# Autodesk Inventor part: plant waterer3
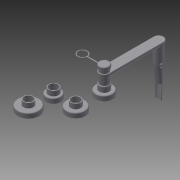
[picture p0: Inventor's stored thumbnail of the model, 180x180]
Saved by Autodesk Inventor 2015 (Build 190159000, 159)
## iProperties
Created: 2014-06
Part Number: plant waterer3
Material: Generic
Document SubType Name: Modeling
Designer: Kay
Density: 1 g/cm^3
Appearance: Default
Author: Kay
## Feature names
1. Loft2
2. Extrusion18
3. Sweep2
4. Extrusion19
5. Extrusion20
6. Extrusion21
7. Extrusion22
8. Extrusion23
9. Extrusion25
10. Extrusion26
11. Extrusion27
12. Extrusion28
13. Fillet1
14. Split1
15. Extrusion30
16. Extrusion31
17. Extrusion32
18. Revolution2
19. Fillet2
20. Extrusion33
21. Extrusion34
22. Revolution3
23. Extrusion35
24. Extrusion36
25. Fillet3
26. Extrusion37
27. Extrusion38
28. Extrusion39
29. Extrusion40
30. Extrusion41
31. Fillet4
32. Extrusion42
33. Extrusion43
34. Extrusion44
35. Revolution4
36. Coil2
37. Fillet5
38. Extrusion45
39. Extrusion46
40. Extrusion47
41. Fillet6
42. Fillet7
43. Fillet8
44. Fillet9
45. Fillet10
46. Fillet11
47. Fillet12
48. Fillet13
49. Extrusion48
50. Extrusion49
51. Extrusion50
52. Revolution5
53. Coil3
54. Fillet14
55. Revolution6
56. Coil4
## Parameters: d45 = 23 mm, d166 = 65 mm, d167 = 7.5 mm, d168 = 15 mm, d169 = 7.5 mm, d170 = -65 mm, d171 = 15 mm, d172 = 18 mm, d173 = 1.5 mm, d174 = 0.5 mm, d175 = 1.5 mm, d176 = -35 mm, d177 = 7.5 mm, d178 = 1.5 mm, d179 = 0, d180 = 90 deg, d181 = 0, d182 = 90 deg, d183 = 0, d184 = 90 deg, d185 = 0, d186 = 90 deg, d187 = 0, d188 = 90 deg, d189 = 0, d190 = 90 deg, d194 = 5 mm, d195 = 5 mm, d196 = 0, d197 = 5 mm, d198 = 5 mm, d199 = 0, d203 = 2 mm, d204 = 5 mm, d205 = 0, d208 = 15 mm, d209 = 1.5 mm, d210 = 2 mm, d211 = 0, d212 = 0, d216 = 15 mm, d219 = 0, d220 = 2 mm, d221 = 2 mm, d222 = 4 mm, d223 = 2 mm, d225 = 0, d227 = 0, d228 = 4 mm, d230 = 1 mm, d231 = 2 mm, d232 = 8.5 mm, d233 = 0, d234 = 8.5 mm, d235 = 0, d240 = 35 mm, d241 = 15 mm, d242 = 1.5 mm, d248 = 15 mm, d249 = 1.5 mm, d252 = 1.5 mm, d254 = 35 mm, d255 = 0, d256 = 2 mm, d257 = 0, d258 = 35 mm, d259 = 0, d260 = 35 mm, d261 = 0, d262 = 2 mm, d264 = 0, d265 = 0, d266 = 2 mm, d267 = -5 mm, d272 = 0, d273 = 1.5 mm, d274 = 2 mm, d275 = 0, d276 = 2 mm, d277 = 0, d278 = 1.5 mm, d279 = 1.5 mm, d280 = 1.5 mm, d281 = 1 mm, d282 = 1.5 mm, d283 = 1.5 mm, d285 = 0, d286 = 1 mm, d287 = 180 deg, d288 = 1.5 mm, d289 = -1.5 mm, d290 = 2 mm, d291 = 35 mm, d292 = 0, d293 = 15 mm, d294 = 1.5 mm, d295 = 1.5 mm, d296 = 15 mm, d297 = 0, d298 = 115 mm, d299 = 1 mm, d300 = 180 deg, d301 = 55 mm, d302 = 1.5 mm, d303 = 5 mm, d304 = 0, d305 = 1.5 mm, d306 = 0, d307 = 2 mm, d308 = 18 mm, d309 = 1.5 mm, d311 = -5 mm, d312 = 18 mm, d313 = 1.5 mm, d314 = 25 mm, d315 = 25 mm, d316 = 1.5 mm, d317 = 0, d319 = 33 mm, d320 = 1.5 mm, d321 = 1.5 mm, d322 = 1.5 mm, d323 = 0, d325 = 0, d327 = 0, d329 = 1.5 mm, d330 = 1.5 mm, d331 = 0, d332 = 2 mm, d333 = 36.8 mm, d334 = 18 mm, d335 = 1.5 mm, d336 = 1.5 mm, d337 = 36.8 mm, d338 = 18 mm, d339 = 1.5 mm, d340 = 1.5 mm, d342 = 0, d343 = 1.5 mm, d344 = 0, d346 = 0, d348 = 8 mm, d349 = 0, d350 = 55 deg, d351 = 0.48025 mm, d352 = 0.48025 mm, Sketch48_ThreadOffset = 0, Sketch48_MajorRadius = 2.22438 mm, d355 = 3 mm, Sketch48_MinorRadius = 0 deg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
